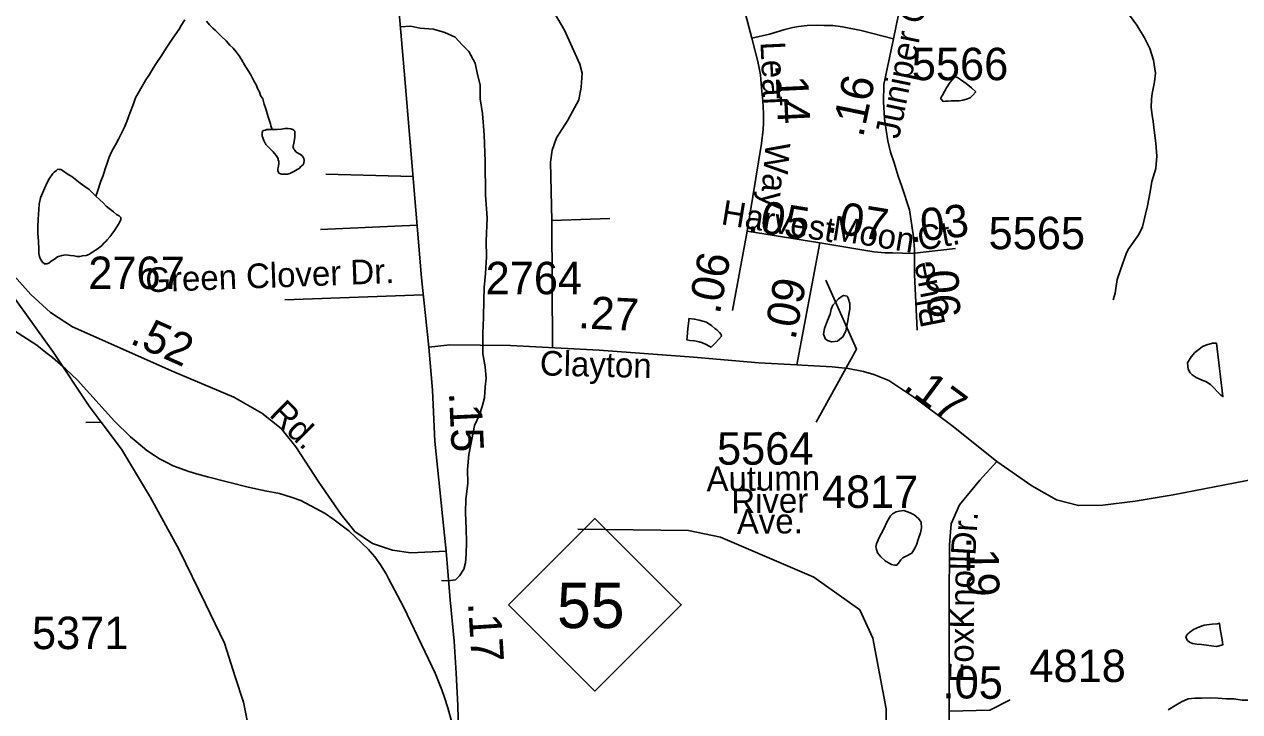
# Model space of a CAD drawing. Extents: x 2001466 to 2224147, y 644118 to 847247.
# Drawn here: x 2071387 to 2076073, y 658253 to 660903 of the extents above; entities that cross this region are included whole.
import ezdxf

# ---------------------------------------------------------------- set-up
doc = ezdxf.new("R2010")
doc.units = 0
for name, color, linetype in [('Exist Hydrographic Creek Single Shore', 7, 'Continuous'), ('Exist Hydrographic Misc Water Feature', 7, 'Continuous'), ('Exist Railroad Mainline', 7, 'Continuous'), ('Exist Road Non-System Type 51', 7, 'Continuous'), ('Exist Road Non-System Type 51 Label', 7, 'Continuous'), ('Exist Road Primary NC Attributed', 7, 'Continuous'), ('Exist Road Primary NC Service Mileage Hundredths English Label', 7, 'Continuous'), ('Exist Road Primary NC Shield CELL', 7, 'Continuous'), ('Exist Road Primary NC Shield Number Label', 7, 'Continuous'), ('Exist Road Secondary Mileage Hundredths English Label', 7, 'Continuous'), ('Exist Road Secondary Type 51 Attributed', 7, 'Continuous'), ('Exist Road Secondary Type 51 Label', 7, 'Continuous'), ('Exist Road Secondary Type 51 Number Label', 7, 'Continuous')]:
    doc.layers.add(name, color=color, linetype=linetype)

msp = doc.modelspace()

# ---------------------------------------------------------------- linework, layer by layer
at = {"layer": 'Exist Hydrographic Creek Single Shore'}
for points in [[(2074431.5, 658772.1), (2074071.9, 658926), (2073947.8, 658951.5), (2073521.9, 658956.9)], [(2074710.2, 658173.9), (2074709.8, 658263.5), (2074658.9, 658536.8), (2074608.9, 658646.1), (2074431.5, 658772.1)]]:
    msp.add_lwpolyline(points, dxfattribs=at)
at = {"layer": 'Exist Hydrographic Misc Water Feature'}
msp.add_line((2071592, 659530.7), (2071734.9, 659373.7), dxfattribs=at)
for points in [[(2071663.1, 660240.1), (2071669.3, 660258.3), (2071683, 660298.4), (2071691, 660320.3), (2071699.2, 660346.2), (2071705.2, 660364.4), (2071714.6, 660390.5), (2071725.1, 660414.5), (2071738.8, 660438.4), (2071750.5, 660460.5), (2071760.7, 660480.5), (2071772.8, 660504.6), (2071782.7, 660528.6), (2071794.4, 660560.5), (2071808.5, 660596.5), (2071816.3, 660620.5), (2071836.4, 660656.4), (2071856.1, 660688.7), (2071870.4, 660710.5), (2071884.2, 660734.7), (2071896.1, 660752.8), (2071918, 660784.7), (2071927.9, 660800.7), (2071940, 660818.7), (2071950.2, 660834.6), (2071960.1, 660850.6), (2071984, 660884.7), (2071991.8, 660898.9), (2072005.8, 660920.7)], [(2072342.5, 660497.4), (2072338.4, 660511.4), (2072336.7, 660519.3), (2072328.3, 660543.3), (2072324.2, 660559.3), (2072318.3, 660577.6), (2072312.5, 660595.6), (2072306.4, 660615.6), (2072298.6, 660629.4), (2072294.5, 660643.4), (2072288.1, 660653.3), (2072282.4, 660667.5), (2072272.1, 660685.2), (2072262.3, 660705.4), (2072247.9, 660729.5), (2072236.1, 660747.1), (2072224.2, 660767.2), (2072216, 660781.4), (2072204.1, 660796.9), (2072192, 660811), (2072179.9, 660823.3), (2072165.9, 660839.2), (2072147.7, 660857), (2072133.9, 660870.9), (2072123.7, 660880.9), (2072114, 660888.9), (2072101.9, 660900.9), (2072089.9, 660914.9)], [(2075585.8, 659840.4), (2075593.4, 659866.4), (2075601.4, 659918.8), (2075622.9, 659982.4), (2075635, 660018.7), (2075643.2, 660034.5), (2075684.6, 660092.7), (2075698.6, 660122.6), (2075710.5, 660170.7), (2075718.2, 660202.8), (2075728.3, 660256.8), (2075734.4, 660296.9), (2075750, 660346.8), (2075753.7, 660394.9), (2075749.8, 660444.6), (2075745.3, 660485), (2075739.6, 660528.9), (2075735.5, 660552.6), (2075731.6, 660582.8), (2075733, 660614.7), (2075735.5, 660636.6), (2075744.9, 660681), (2075748.8, 660714.9), (2075740.6, 660764.8), (2075726.7, 660810.7), (2075706.6, 660850.7), (2075676.6, 660900.6), (2075647.9, 660938.2)], [(2074957.1, 660680.3), (2074943.4, 660658.1), (2074935.4, 660644.2), (2074927.2, 660630.1), (2074921.2, 660620), (2074921.4, 660616.3), (2074929.6, 660606.2), (2074939.3, 660606.4), (2074949.5, 660606.4), (2074961.4, 660608.3), (2074975.3, 660608.6), (2074991.5, 660608.6), (2075005.5, 660610.5), (2075019.4, 660614.5), (2075033.6, 660620.4), (2075043.4, 660628.7), (2075055.5, 660642.7), (2075038.9, 660658.6), (2075019.2, 660674.6), (2074997.1, 660690.5), (2074984.8, 660698.4), (2074974.9, 660700.3), (2074957.1, 660680.3)], [(2072342.5, 660497.4), (2072354.4, 660497.6), (2072362.4, 660497.6), (2072378.6, 660499.6), (2072392.3, 660501.6), (2072404.4, 660501.8), (2072414.7, 660499.8), (2072422.4, 660497.8), (2072426.8, 660495.5), (2072430.2, 660491.7), (2072430.6, 660485.6), (2072430.4, 660477.5), (2072430.6, 660467.8), (2072428.8, 660459.5), (2072426.3, 660445.7), (2072424.5, 660433.8), (2072424.3, 660427.8), (2072426.8, 660421.7), (2072430.6, 660417.5), (2072434.7, 660411.6), (2072446.6, 660403.7), (2072452.6, 660401.6), (2072456.7, 660397.7), (2072462.4, 660391.6), (2072464.5, 660386), (2072466.9, 660379.9), (2072464.9, 660367.7), (2072461, 660359.7), (2072454.8, 660355.8), (2072446.6, 660347.7), (2072438.9, 660343.6), (2072432.9, 660339.6), (2072426.8, 660335.7), (2072410.6, 660327.6), (2072402.6, 660325.6), (2072395, 660325.5), (2072386.8, 660325.5), (2072378.8, 660325.6), (2072368.7, 660329.5), (2072365, 660339.4), (2072364.6, 660345.5), (2072366.9, 660355.8), (2072368.7, 660367.6), (2072368.9, 660375.7), (2072366.5, 660379.7), (2072366.7, 660385.8), (2072358.5, 660397.6), (2072352.5, 660405.4), (2072346.8, 660411.6), (2072332.6, 660425.4), (2072324.4, 660433.5), (2072318.3, 660439.4), (2072314.6, 660447.6), (2072310.3, 660455.6), (2072306.4, 660465.5), (2072304.3, 660473.5), (2072304.5, 660487.3), (2072308.6, 660493.6), (2072316.6, 660495.6), (2072322.4, 660497.6), (2072328.3, 660497.5), (2072336.5, 660497.5), (2072342.5, 660497.4)], [(2071663.1, 660240.1), (2071679.1, 660226.3), (2071691.2, 660214.4), (2071703.3, 660202.5), (2071731, 660180.4), (2071742.9, 660170.5), (2071753, 660164.5), (2071759.3, 660158.7), (2071759.3, 660150.6), (2071753.6, 660136.4), (2071743.5, 660122.5), (2071735.1, 660108.4), (2071725.3, 660094.4), (2071717.5, 660084.2), (2071707.4, 660072.4), (2071701.5, 660066.4), (2071695.7, 660060.4), (2071685.7, 660050.6), (2071671.8, 660038.5), (2071661.3, 660032.4), (2071649.8, 660024.4), (2071635.7, 660016.4), (2071625.6, 660012.2), (2071611.7, 660010.3), (2071601.6, 660008.2), (2071589.7, 660008.3), (2071579.5, 660010.3), (2071565.7, 660012), (2071547.3, 660014.3), (2071531.7, 660011.9), (2071515.5, 660006.2), (2071503.4, 659997.9), (2071491.5, 659990), (2071481.7, 659982.1), (2071473.7, 659980.1), (2071465.7, 659980.1), (2071457.7, 659986.2), (2071449.9, 659997.9), (2071445.6, 660007.9), (2071443.3, 660020), (2071443.3, 660035.8), (2071441.7, 660066), (2071439.4, 660098), (2071439.4, 660124), (2071441.3, 660150.1), (2071441.5, 660171.9), (2071443.1, 660189.9), (2071445.2, 660209.9), (2071449.3, 660234), (2071465.1, 660269.8), (2071477, 660296), (2071483.3, 660308), (2071497.3, 660327.7), (2071502.8, 660333.8), (2071511, 660339.8), (2071516.9, 660344.2), (2071522.9, 660344.1), (2071529.2, 660344), (2071535, 660339.9), (2071556.9, 660324), (2071570.9, 660316.2), (2071603.1, 660290.2), (2071621.1, 660278.2), (2071636.9, 660266.4), (2071649, 660254.4), (2071663.1, 660240.1)], [(2074498, 659805.3), (2074504.1, 659821), (2074515.8, 659833), (2074526.1, 659845.3), (2074540, 659855.3), (2074545.8, 659857.2), (2074559.5, 659855.1), (2074563.8, 659847.2), (2074569.8, 659827.3), (2074570, 659805.3), (2074566.1, 659785.2), (2074561.8, 659759.5), (2074554.2, 659721.3), (2074544.1, 659699.3), (2074522.4, 659681.1), (2074500.4, 659679.2), (2074486.7, 659682.9), (2074476, 659688.9), (2074468.5, 659709.1), (2074472.1, 659730.9), (2074484.2, 659761.1), (2074494.3, 659785.2), (2074498, 659805.3)], [(2071213.7, 659789.3), (2071289.9, 659758.3), (2071435.9, 659665.9), (2071470.6, 659638.4)], [(2071213.7, 659789.3), (2071289.9, 659758.3), (2071435.9, 659665.9), (2071470.6, 659638.4)], [(2074017.3, 659754.8), (2074037.6, 659740.8), (2074049.5, 659730.9), (2074057.5, 659724.8), (2074067.8, 659714.7), (2074073.7, 659706.9), (2074075.6, 659700.9), (2074053.6, 659676.7), (2074035.4, 659658.8), (2074027.6, 659662.8), (2074015.9, 659668.6), (2074001.6, 659674.9), (2073989.5, 659678.7), (2073971.4, 659682.7), (2073953.8, 659684.5), (2073941.5, 659686.8), (2073943.5, 659696.6), (2073945.4, 659730.8), (2073949.5, 659760.6), (2073949.7, 659768.7), (2073971.4, 659766.7), (2073989.5, 659762.7), (2074017.3, 659754.8)], [(2071470.6, 659638.4), (2071496.2, 659618.1), (2071547.9, 659573.2), (2071592, 659530.7)], [(2071470.6, 659638.4), (2071496.2, 659618.1), (2071547.9, 659573.2), (2071592, 659530.7)], [(2075983.8, 659673.8), (2076008.6, 659467.7), (2076000.6, 659473.7), (2075960.6, 659513.9), (2075942.6, 659525.5), (2075930.5, 659529.4), (2075904.8, 659541.4), (2075890.3, 659551.3), (2075882.3, 659559.4), (2075874.5, 659573.6), (2075872, 659597.4), (2075886.4, 659621.6), (2075899.9, 659637.4), (2075916.1, 659649.6), (2075930.3, 659661.6), (2075946.3, 659667.7), (2075968, 659673.8), (2075983.8, 659673.8)], [(2071734.9, 659373.7), (2071796.8, 659313.1), (2071818.2, 659295.2)], [(2071734.9, 659373.7), (2071796.8, 659313.1), (2071818.2, 659295.2)], [(2071818.2, 659295.2), (2071860, 659260.4), (2071889.5, 659240.5)], [(2071818.2, 659295.2), (2071860, 659260.4), (2071889.5, 659240.5)], [(2071889.5, 659240.5), (2071908.8, 659227.5), (2071932, 659215.9)], [(2071889.5, 659240.5), (2071908.8, 659227.5), (2071932, 659215.9)], [(2071932, 659215.9), (2071960.9, 659201.3), (2072022, 659179.1), (2072051.1, 659170.6)], [(2071932, 659215.9), (2071960.9, 659201.3), (2072022, 659179.1), (2072051.1, 659170.6)], [(2072051.1, 659170.6), (2072094.2, 659158), (2072251, 659118.4)], [(2072051.1, 659170.6), (2072094.2, 659158), (2072251, 659118.4)], [(2072251, 659118.4), (2072315.8, 659104.1), (2072371, 659094.2), (2072415.9, 659079.9)], [(2072251, 659118.4), (2072315.8, 659104.1), (2072371, 659094.2), (2072415.9, 659079.9)], [(2072415.9, 659079.9), (2072454, 659067.8), (2072547.7, 659016.7), (2072576.2, 658995.9)], [(2072415.9, 659079.9), (2072454, 659067.8), (2072547.7, 659016.7), (2072576.2, 658995.9)], [(2074774.8, 658846.3), (2074766.6, 658838.2), (2074761.1, 658830.1), (2074751, 658818.2), (2074742.8, 658818.3), (2074730.9, 658820.1), (2074706.7, 658833.9), (2074689.1, 658850), (2074676.8, 658866), (2074672.5, 658878), (2074670.8, 658888), (2074672.7, 658899.9), (2074682.7, 658924), (2074700.4, 658955.7), (2074714.3, 658986.1), (2074726.4, 659008.1), (2074734.6, 659015.8), (2074748.4, 659023.9), (2074760, 659026.2), (2074778.3, 659028.3), (2074802.5, 659020.2), (2074818.7, 659012.4), (2074834.5, 658998.3), (2074844.5, 658984.2), (2074846.4, 658962.4), (2074842.7, 658942.3), (2074834.7, 658920.4)], [(2072576.2, 658995.9), (2072638.8, 658950.1), (2072689, 658902.9)], [(2072576.2, 658995.9), (2072638.8, 658950.1), (2072689, 658902.9)], [(2072689, 658902.9), (2072714.9, 658878.4), (2072730, 658860.1)], [(2072689, 658902.9), (2072714.9, 658878.4), (2072730, 658860.1)], [(2074834.7, 658920.4), (2074826.9, 658896.4), (2074823, 658888.1), (2074816.8, 658876.4), (2074808.8, 658864.3), (2074800.8, 658860.2), (2074794.7, 658856.2), (2074786.7, 658852.2), (2074774.8, 658846.3)], [(2072730, 658860.1), (2072738.8, 658849.4), (2072761, 658818.9)], [(2072730, 658860.1), (2072738.8, 658849.4), (2072761, 658818.9)], [(2072761, 658818.9), (2072781.9, 658784.1), (2072792.8, 658764.2)], [(2072761, 658818.9), (2072781.9, 658784.1), (2072792.8, 658764.2)], [(2072792.8, 658764.2), (2072804.9, 658742.5), (2072848.7, 658657.1), (2072932.4, 658482.1)], [(2072792.8, 658764.2), (2072804.9, 658742.5), (2072848.7, 658657.1), (2072932.4, 658482.1)], [(2076005.7, 658530), (2076007.6, 658510.3), (2075983.6, 658504.2), (2075953.6, 658507.8), (2075925.8, 658511.7), (2075907.7, 658513.6), (2075891.5, 658515.6), (2075879.8, 658521.5), (2075871.8, 658527.5), (2075867.7, 658533.8), (2075865.7, 658541.9), (2075871.6, 658551.5), (2075881.5, 658559.8), (2075895.4, 658569.8), (2075917.6, 658579.9), (2075935.6, 658586), (2075967.2, 658590.2), (2075987.5, 658592), (2075995.5, 658594), (2075997.3, 658572.2), (2076005.7, 658530)], [(2072932.4, 658482.1), (2072971, 658401.3), (2072996.8, 658337), (2073007, 658307.3)], [(2072932.4, 658482.1), (2072971, 658401.3), (2072996.8, 658337), (2073007, 658307.3)], [(2073007, 658307.3), (2073020.8, 658267.5), (2073034.1, 658216.6)], [(2073007, 658307.3), (2073020.8, 658267.5), (2073034.1, 658216.6)]]:
    msp.add_lwpolyline(points, dxfattribs=at)
at = {"layer": 'Exist Railroad Mainline'}
msp.add_lwpolyline([(2071263.8, 659965), (2071497.8, 659641.2), (2071638, 659431.2), (2071684.2, 659369.4), (2071762.2, 659265.2), (2071874.2, 659079.2), (2071984.3, 658877.3), (2072086.5, 658669.3), (2072158.6, 658517.2), (2072200.5, 658387.3), (2072232.7, 658289.3), (2072255.3, 658173.9)], dxfattribs=at)
at = {"layer": 'Exist Road Non-System Type 51'}
for p, q in [((2072886.1, 660316.5), (2072549.4, 660325.5)), ((2072529, 660111.9), (2072901.6, 660129)), ((2072925.4, 659860.8), (2072391.5, 659840.7)), ((2071684.2, 659369.4), (2071623.9, 659368.2))]:
    msp.add_line(p, q, dxfattribs=at)
for points in [[(2073420.8, 660146.7), (2073415.5, 660372.4), (2073422.2, 660417.9), (2073439.5, 660466), (2073482.3, 660534.2), (2073525.1, 660611.8), (2073534.4, 660661.2), (2073538.4, 660714.7), (2073529.1, 660749.5), (2073470.3, 660880.5), (2073392.8, 661012.9), (2073372.7, 661039.7), (2073336.6, 661074.4)], [(2072837.9, 660893.8), (2072877, 660896.8), (2072912.8, 660888.1), (2072964.8, 660885), (2073008.5, 660872.1), (2073048.1, 660853.3), (2073075.5, 660824.8), (2073101, 660798.3), (2073126.1, 660753.8), (2073135.2, 660709.6), (2073144.4, 660669.4), (2073145.3, 660615.4), (2073154.1, 660559.2), (2073160.5, 660477.1), (2073164.4, 660375), (2073165.7, 660244.9), (2073171.9, 660156.8), (2073168.1, 660066.9), (2073168.9, 660006.9), (2073165.6, 659942.9), (2073160.5, 659889.1), (2073159.5, 659841.1), (2073158.1, 659773.1), (2073154.9, 659711.2), (2073155.3, 659633.2)], [(2073420.8, 660146.7), (2073645.3, 660154.7)], [(2073423.6, 659656.4), (2073420.8, 660146.7)], [(2073155.3, 659633.2), (2073164.3, 659583), (2073167.4, 659538.9), (2073164.7, 659505), (2073161.8, 659463), (2073153.1, 659429.2), (2073142.5, 659397.4), (2073123.6, 659355.8), (2073112.5, 659302), (2073101.4, 659244.2), (2073096.2, 659186.4), (2073097.1, 659132.3), (2073089.9, 659072.5), (2073088.8, 659020.5), (2073091.5, 658958.4), (2073092.5, 658906.4), (2073091.5, 658860.4), (2073088.9, 658826.5), (2073082.4, 658802.6), (2073065.8, 658777), (2073049.5, 658761.3), (2073039.5, 658759.5), (2073021.5, 658757.9), (2072995.5, 658758.4)], [(2075797, 658259.9), (2075827, 658278.1), (2075848.8, 658290.2), (2075874.9, 658302.3), (2075900.7, 658304.4), (2075926.7, 658304.4), (2075958.8, 658306.4), (2075990.7, 658304.5), (2076020.7, 658302.7), (2076050.7, 658302.7), (2076082.8, 658296.9), (2076118.8, 658296.9), (2076164.7, 658295.2), (2076208.7, 658295.3), (2076242.7, 658295.4), (2076292.8, 658297.6), (2076336.7, 658293.7), (2076352.7, 658293.8), (2076392.7, 658293.8), (2076440.8, 658290)]]:
    msp.add_lwpolyline(points, dxfattribs=at)
at = {"layer": 'Exist Road Primary NC Attributed'}
for points in [[(2072947.2, 659659), (2072918.4, 659926), (2072852.5, 660724.1), (2072819, 661113.6), (2072765.6, 661624.7), (2072734.2, 662020.6), (2072716.4, 662380.8), (2072706, 662577.7), (2072680.8, 662806), (2072654.7, 663075.1)], [(2073014.2, 658871.5), (2073004.7, 658958.4), (2072970.7, 659296.6), (2072961.3, 659492.5), (2072947.2, 659659)], [(2073037.2, 657953), (2073051.8, 658059.8), (2073061.3, 658175), (2073058.6, 658276.6), (2073052.4, 658401.2), (2073044.5, 658524.8), (2073028.8, 658684), (2073014.2, 658871.5)]]:
    msp.add_lwpolyline(points, dxfattribs=at)
at = {"layer": 'Exist Road Primary NC Shield CELL'}
msp.add_lwpolyline([(2073254.1, 658665), (2073587.1, 658998), (2073920.1, 658665), (2073587.1, 658332)], close=True, dxfattribs=at)
at = {"layer": 'Exist Road Secondary Type 51 Attributed'}
msp.add_line((2074366.1, 659590.3), (2074455, 660060.3), dxfattribs=at)
for points in [[(2074192.9, 660849.7), (2074153.2, 660997.5), (2074089.9, 661204.9), (2074049.5, 661355.2), (2074045.1, 661388), (2074044, 661420.2), (2074046.2, 661436.6), (2074053.3, 661457.9)], [(2074840.4, 661342.8), (2074738, 660847.2)], [(2074192.9, 660849.7), (2074261, 660865.4), (2074319.9, 660884), (2074350.5, 660891.3), (2074372.5, 660895.2), (2074406, 660898.6), (2074444.6, 660899.7), (2074470.9, 660899.3), (2074504.1, 660898.7), (2074542.3, 660893.1), (2074613.9, 660879), (2074738, 660847.2)], [(2074174.1, 660106.1), (2074229, 660444.2), (2074235.6, 660498.4), (2074237.7, 660522.4), (2074237.2, 660561.1), (2074235, 660607.5), (2074229.6, 660658.9), (2074225.2, 660709.2), (2074216, 660759.6), (2074192.9, 660849.7)], [(2074738, 660847.2), (2074701.6, 660671.3), (2074699.5, 660605.1), (2074704.3, 660540.1), (2074710.1, 660494.8), (2074717, 660454.1), (2074727, 660410.2), (2074740.8, 660368.9), (2074756.1, 660318.1), (2074770.9, 660277.6), (2074800, 660187.6), (2074815.3, 660083.3), (2074819.1, 660035.1), (2074819.1, 660020.3)], [(2070967.3, 660474.1), (2071035.3, 660378.5), (2071305.5, 659981.4), (2071412.1, 659862), (2071488.1, 659792.3), (2071572.6, 659737.4), (2071963.7, 659563.1), (2072194.8, 659465.9), (2072303.5, 659403.6), (2072377.4, 659344.4), (2072433.9, 659274.7), (2072522.6, 659137.4), (2072609.1, 659012.8), (2072661.9, 658947.3), (2072729.4, 658900.8), (2072807.5, 658875.4), (2072877.2, 658864.9), (2073014.2, 658871.5)], [(2074117.2, 659800), (2074171.7, 660091.2), (2074174.1, 660106.1)], [(2074174.1, 660106.1), (2074455, 660060.3)], [(2074455, 660060.3), (2074662.3, 660026.5), (2074705.3, 660022.1), (2074734.3, 660022.1), (2074811.6, 660019.5), (2074819.1, 660020.3)], [(2074819.1, 660020.3), (2074977.5, 660038.3)], [(2074819.1, 660020.3), (2074819.1, 659938.7), (2074829.6, 659723.9)], [(2074366.1, 659590.3), (2074219.7, 659598), (2073967.2, 659620), (2073604.2, 659647.5), (2073262.2, 659664.4), (2073027.3, 659667.5), (2072947.2, 659659)], [(2075136.7, 659217.6), (2074968.9, 659352.8), (2074821.1, 659462.6), (2074720.3, 659530.2), (2074662.3, 659552.4), (2074623, 659564.2), (2074563.3, 659575.7), (2074501.5, 659582.6), (2074384.7, 659589.4), (2074366.1, 659590.3)], [(2077955.9, 659170), (2077754.3, 659185.9), (2077370.1, 659219.7), (2077045, 659249.3), (2076793.3, 659260.9), (2076678.3, 659256.7), (2076475.6, 659220.7), (2076095.6, 659143.6), (2075816.5, 659088.7), (2075669.7, 659064.4), (2075545.2, 659048.6), (2075451.3, 659047.5), (2075366.8, 659069.7), (2075271.3, 659123.6), (2075136.7, 659217.6)], [(2075136.7, 659217.6), (2075070.8, 659145.8), (2074992.7, 659050.7), (2074961, 658976.8), (2074954.7, 658896.5), (2074952.5, 658672.6), (2074953.1, 658422.2), (2074953.6, 658255.4)], [(2074953.6, 658255.4), (2075109.8, 658258.5), (2075187.9, 658298.7)], [(2074953.6, 658255.4), (2074952.5, 658069.5), (2074976.8, 657990.2)]]:
    msp.add_lwpolyline(points, dxfattribs=at)
at = {"layer": 'Exist Road Secondary Type 51 Number Label'}
msp.add_lwpolyline([(2074477.1, 659916.9), (2074595.6, 659650.3), (2074440.1, 659368.9)], dxfattribs=at)

# ---------------------------------------------------------------- texts
at = {"layer": 'Exist Road Non-System Type 51 Label'}
msp.add_text('Green Clover Dr.', height=95, rotation=2.1642, dxfattribs=at).set_placement((2071855.9, 659869.7))
at = {"layer": 'Exist Road Primary NC Service Mileage Hundredths English Label'}
for s, rotation, p in [('.15', 272.7534, (2073024.3, 659483.3)), ('.17', 273.6349, (2073097.7, 658672.6))]:
    msp.add_text(s, height=125, rotation=rotation, dxfattribs=at).set_placement(p)
at = {"layer": 'Exist Road Primary NC Shield Number Label'}
msp.add_text('55', height=175, dxfattribs=at).set_placement((2073441.2, 658575.3))
at = {"layer": 'Exist Road Secondary Mileage Hundredths English Label'}
for s, rotation, p in [('.14', 272.6931, (2074282.4, 660749)), ('.16', 78.3254, (2074621, 660464.1)), ('.05', 350.738, (2074173, 660108.3)), ('.07', 350.738, (2074476.9, 660103.4)), ('.03', 6.4711, (2074803, 660061.5)), ('.06', 79.3944, (2074068.3, 659782.1)), ('.06', 272.8083, (2074860.9, 660000.6)), ('.09', 79.294, (2074359.7, 659683.1)), ('.27', 357.1709, (2073521, 659731.8)), ('.52', 335.9795, (2071790.1, 659674.9)), ('.17', 323.3736, (2074772.6, 659499.4)), ('.19', 270.8271, (2075019.2, 658927.9)), ('.05', 359.235, (2074927.2, 658305))]:
    msp.add_text(s, height=125, rotation=rotation, dxfattribs=at).set_placement(p)
at = {"layer": 'Exist Road Secondary Type 51 Label'}
for s, rotation, p in [('Juniper Ct.', 78.3253, (2074759.3, 660458.3)), ('Leaf', 272.6931, (2074225.3, 660835.1)), ('Way', 265.303, (2074246.1, 660450.5)), ('Harvest ', 350.738, (2074070.4, 660133)), ('Moon', 350.738, (2074497.5, 660073)), ('Ct.', 9.9677, (2074839.9, 660029.3)), ('Blue', 101.1673, (2074939.2, 659746.2)), ('Clayton', 358.6421, (2073374.3, 659549.7)), ('Rd.', 315.3835, (2072327.7, 659395.6)), ('Autumn', 0.547, (2074017.9, 659103)), ('River', 0.547, (2074113.7, 659017.8)), ('Ave.', 0.547, (2074134.9, 658938.4)), ('Dr.', 86.5214, (2075054.3, 658853.3)), ('Knoll', 89.3775, (2075048.4, 658572.6)), ('Fox', 89.3775, (2075045.9, 658363.9))]:
    msp.add_text(s, height=95, rotation=rotation, dxfattribs=at).set_placement(p)
at = {"layer": 'Exist Road Secondary Type 51 Number Label'}
for s, p in [('5566', (2074809, 660687.9)), ('5565', (2075105.1, 660036)), ('2767', (2071634, 659882.7)), ('2764', (2073165.9, 659862.6)), ('5564', (2074058, 659205.3)), ('4817', (2074462.3, 659038.5)), ('5371', (2071416.8, 658494.1)), ('4818', (2075262.4, 658367.2))]:
    msp.add_text(s, height=125, dxfattribs=at).set_placement(p)

doc.saveas('drawing.dxf')
